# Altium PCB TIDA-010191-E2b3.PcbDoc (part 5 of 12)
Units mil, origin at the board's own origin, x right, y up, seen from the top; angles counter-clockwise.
Board outline 9842.52 x 9842.4 mil, 6 copper layers (Layer 1 - Top Layer, Layer 2 - GND Layer, Layer 3 - Signal, Layer 4 - Signal, Layer 5 - GND, Bottom Layer), stack 59.9 mil thick; 1178 components, 642 nets, 3329 pads, 2967 vias.
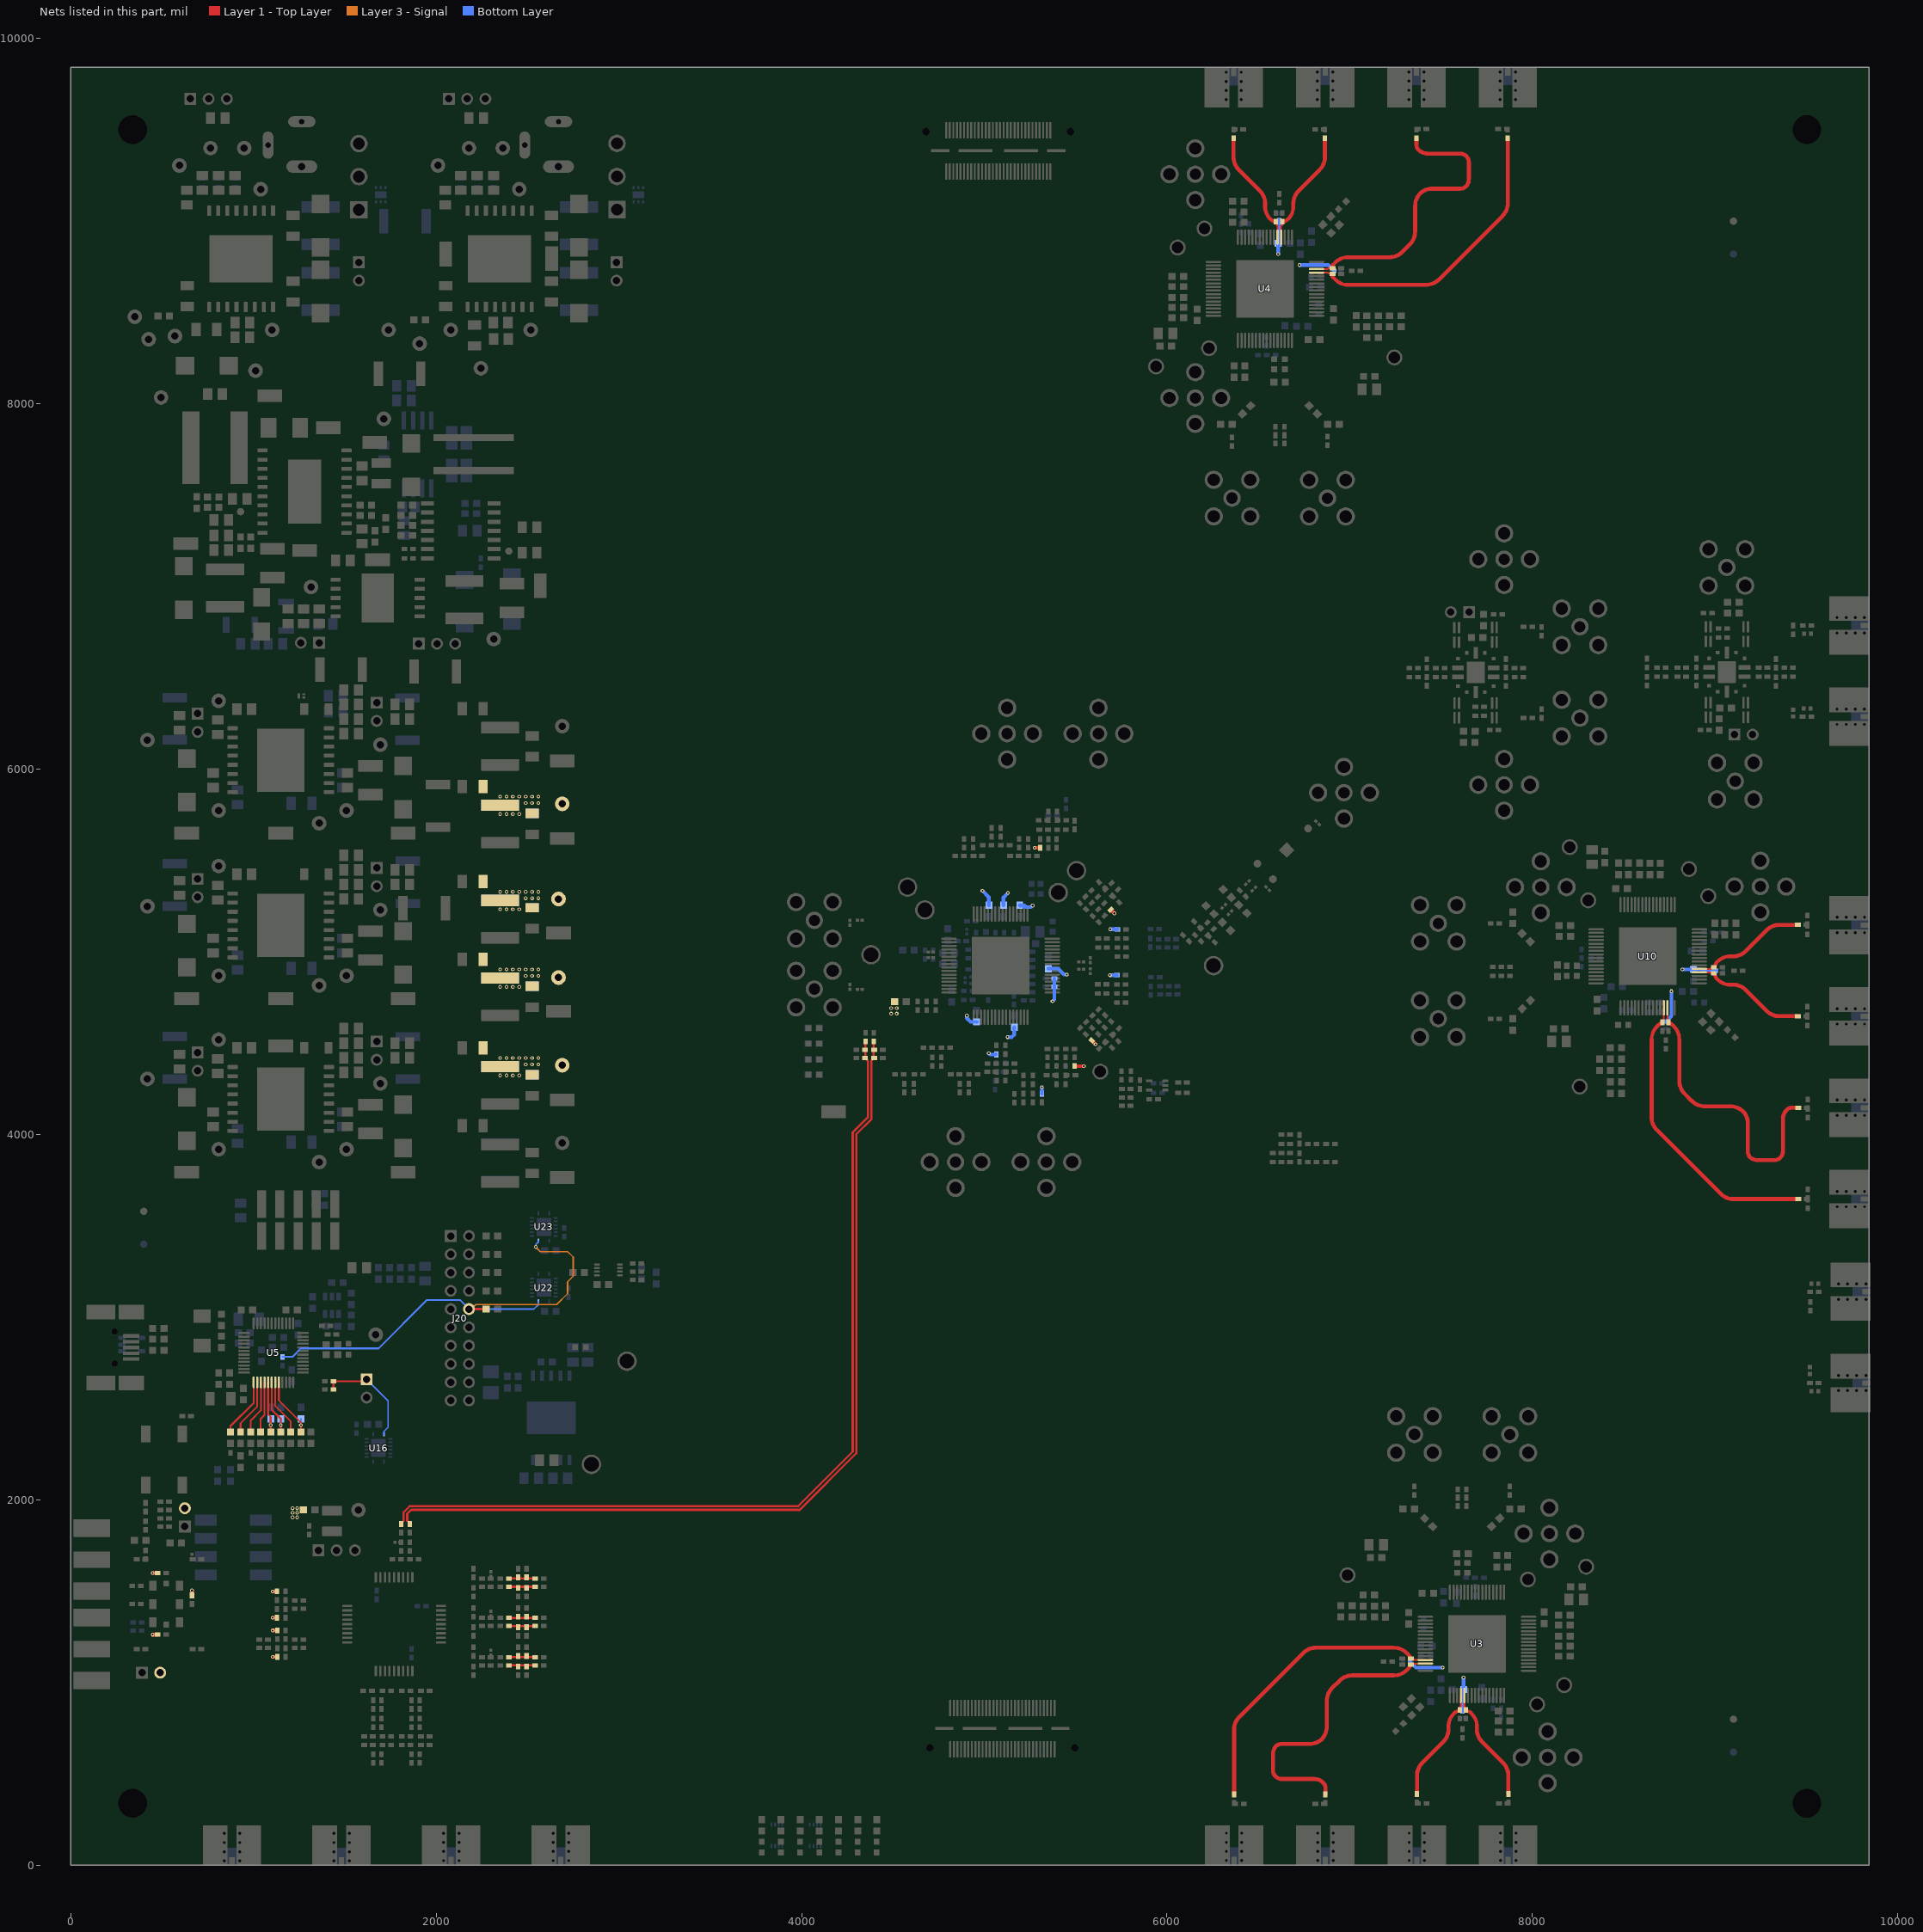
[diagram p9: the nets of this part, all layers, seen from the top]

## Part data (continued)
R5 R13 R14 R21 R22 R29 R30 R31 R32 R47 R48 R49 R50 R286 R287 R288 R289 R356: library part CMP-0026833-3, "RES, 120, 5%, 0.063 W, AEC-Q200 Grade 0, 0402", Manufacturer=Vishay-Dale, PartNumber=CRCW0402120RJNED, Power_W=63mW, Supplier Part Number 1=541-120JCT-ND, TempCo="200 ppm/C", Tolerance_%=5%, Value2=0.063W, Value_Code=120R, ValueDisplayed=120
R11 R12 R15 R16 R23 R24 R60 R61 R64 R65 R66 R67: library part CMP-0026882-3, "RES, 240, 5%, 0.063 W, AEC-Q200 Grade 0, 0402", Manufacturer=Vishay-Dale, PartNumber=CRCW0402240RJNED, Power_W=63mW, Supplier Part Number 1=541-240JCT-ND, TempCo="200 ppm/C", Tolerance_%=5%, Value2=0.063W, Value_Code=240R, ValueDisplayed=240
R17 R18 R58 R59: library part CMP-0026878-3, "RES, 220, 5%, 0.063 W, AEC-Q200 Grade 0, 0402", Manufacturer=Vishay-Dale, PartNumber=CRCW0402220RJNED, Power_W=63mW, Supplier Part Number 1=541-220JCT-ND, TempCo="200 ppm/C", Tolerance_%=5%, Value2=0.063W, Value_Code=220R, ValueDisplayed=220
R26 R68 R69 R71 R72 R73 R74 R75 R76 R81 R84 R92 R126 R127 R130 R132 R135 R136 R166 R203 R208 R209 R216 R233 R238 R239 R240 R242 R243 R244 R245 R246 R247 R249 R269 R271 R272 R273 R280 R295 R301 R316 R319 R325 R331 R332 R350 R352 R353 R355 R358 R359 R360 R389 R494 R497 R500: "RES, 0, 5%, 0.063 W, AEC-Q200 Grade 0, 0402", Manufacturer=Vishay-Dale, PartNumber=CRCW04020000Z0ED, Power_W=63mW, Supplier Part Number 1=541-0.0JCT-ND, TempCo="200 ppm/C", Tolerance_%=5%, Value2=0.063W, Value_Code=0000, ValueDisplayed=0
R28: library part CMP-0027814-1, "RES, 620, 1%, 0.05 W, 0201", Manufacturer="Yageo America", PartNumber=RC0201FR-07620RL, Power_W=50mW, Supplier Part Number 1=YAG2348CT-ND, TempCo="200 ppm/C", Tolerance_%=1%, Value2=0.05W, Value_Code=620R, ValueDisplayed=620
R34 R40 R270 R299: library part CMP-0025998-3, "RES, 130, 1%, 0.063 W, AEC-Q200 Grade 0, 0402", Manufacturer=Vishay-Dale, PartNumber=CRCW0402130RFKED, Power_W=63mW, Supplier Part Number 1=541-130LCT-ND, TempCo="100 ppm/C", Tolerance_%=1%, Value2=0.063W, Value_Code=130R, ValueDisplayed=130
R35 R343: library part CMP-0026658-1, "RES, 10.0 k, 1%, 0.1 W, 0402", Manufacturer=Panasonic, PartNumber=ERJ-2RKF1002X, Power_W=100mW, Supplier Part Number 1=P10.0KLCT-ND, TempCo="100 ppm/C", Tolerance_%=1%, Value2=0.1W, Value_Code=10k0, ValueDisplayed=10.0k
R36 R38 R180 R220: library part Resistor, "RES, 0, 5%, 0.063 W, 0402", Manufacturer=Panasonic, Power_W=63mW, Supplier Part Number 1=P0.0JCT-ND, TempCo="600 ppm/C", Tolerance_%=5%, Value2=0.063W, Value_Code=0000, ValueDisplayed=0
R43 R44 R51 R370: library part CMP-0026834-3, "RES, 12 k, 5%, 0.063 W, AEC-Q200 Grade 0, 0402", Manufacturer=Vishay-Dale, PartNumber=CRCW040212K0JNED, Power_W=63mW, Supplier Part Number 1=541-12KJCT-ND, TempCo="200 ppm/C", Tolerance_%=5%, Value2=0.063W, Value_Code=12k0, ValueDisplayed=12k
R52: library part CMP-0027649-1, "RES, 39.0 k, 1%, 0.05 W, 0201", Manufacturer="Yageo America", PartNumber=RC0201FR-0739KL, Power_W=50mW, Supplier Part Number 1=YAG2641CT-ND, TempCo="200 ppm/C", Tolerance_%=1%, Value2=0.05W, Value_Code=39k0, ValueDisplayed=39.0k
R53 R104 R113 R277 R318 R348 R351: library part CMP-0025825-4, "RES, 51, 5%, 0.1 W, AEC-Q200 Grade 0, 0603", Manufacturer=Vishay-Dale, PartNumber=CRCW060351R0JNEA, Power_W=100mW, Supplier Part Number 1=541-51GCT-ND, TempCo="200 ppm/C", Tolerance_%=5%, Value2=0.1W, Value_Code=51R0, ValueDisplayed=51
R77 R78 R79 R80: library part CMP-0022588-5, "RES, 750, 1%, 0.1 W, AEC-Q200 Grade 0, 0603", Manufacturer=Vishay-Dale, PartNumber=CRCW0603750RFKEA, Power_W=100mW, Supplier Part Number 1=541-750HCT-ND, TempCo="100 ppm/C", Tolerance_%=1%, Value2=0.1W, Value_Code=750R, ValueDisplayed=750
R82 R86 R93 R97 R224 R230 R258 R260 R261 R265 R315 R327: "RES, 50, 0.1%, 0.05 W, 0402", Manufacturer=Vishay-Dale, PartNumber=FC0402E50R0BST1, Power_W=50mW, Supplier Part Number 1=FC0402-50BWCT-ND, TempCo="25 ppm/C", Tolerance_%=0.1%, Value2=0.05W, Value_Code=50R0, ValueDisplayed=50
R83 R85 R87 R88 R89 R91 R107 R112 R178 R211 R212 R226 R227 R228 R231 R232 R235 R251 R252 R253 R254 R255 R256 R257 R259 R262 R281 R304 R317 R333 R354 R372 R559 R560: library part CMP-0025697-4, "RES, 0, 5%, 0.1 W, AEC-Q200 Grade 0, 0603", Manufacturer=Vishay-Dale, PartNumber=CRCW06030000Z0EA, Power_W=100mW, Supplier Part Number 1=541-0.0GCT-ND, TempCo="200 ppm/C", Tolerance_%=5%, Value2=0.1W, Value_Code=0000, ValueDisplayed=0
R90 R250 R274: library part CMP-0025698-4, "RES, 100 k, 5%, 0.1 W, AEC-Q200 Grade 0, 0603", Manufacturer=Vishay-Dale, PartNumber=CRCW0603100KJNEA, Power_W=100mW, Supplier Part Number 1=541-100KGCT-ND, TempCo="200 ppm/C", Tolerance_%=5%, Value2=0.1W, Value_Code=100k
R94 R263 R321: library part CMP-0025904-5, "RES, 270, 5%, 0.1 W, 0603", Manufacturer=Yageo, PartNumber=RC0603JR-07270RL, Power_W=100mW, Supplier Part Number 1=311-270GRCT-ND, TempCo="100 ppm/C", Tolerance_%=5%, Value2=0.1W, Value_Code=270R, ValueDisplayed=270
R95 R320: "RES, 0, 5%, 0.1 W, AEC-Q200 Grade 0, 0603", Manufacturer=Vishay-Dale, PartNumber=CRCW06030000Z0EA, Power_W=100mW, Supplier Part Number 1=541-0.0GCT-ND, TempCo="200 ppm/C", Tolerance_%=5%, Value2=0.1W, Value_Code=0000, ValueDisplayed=0
R96 R264 R322: library part CMP-0025710-4, "RES, 120, 5%, 0.1 W, AEC-Q200 Grade 0, 0603", Manufacturer=Vishay-Dale, PartNumber=CRCW0603120RJNEA, Power_W=100mW, Supplier Part Number 1=541-120GCT-ND, TempCo="200 ppm/C", Tolerance_%=5%, Value2=0.1W, Value_Code=120R, ValueDisplayed=120
R98 R101: "RES, 0, 5%, .05 W, AEC-Q200 Grade 0, 0201", Manufacturer=Panasonic, PartNumber=ERJ-1GN0R00C, Power_W=50mW, Supplier Part Number 1=P15979CT-ND, TempCo=ppm/C, Tolerance_%=5%, Value2=.05W, Value_Code=0000, ValueDisplayed=0
R99 R100: library part CMP-0027139-3, "RES, 51, 5%, 0.05 W, 0201", Manufacturer="Yageo America", Power_W=50mW, Supplier Part Number 1=311-51NCT-ND, TempCo="200 ppm/C", Tolerance_%=5%, Value2=0.05W, Value_Code=51R0, ValueDisplayed=51
R102 R109 R154 R156 R157 R158 R159 R181 R185 R186 R187 R188 R189 R206 R207 R225 R279 R300 R313 R349 R538 R539 R540 R541: "RES, 100, 1%, 0.1 W, AEC-Q200 Grade 0, 0603", Manufacturer=Vishay-Dale, PartNumber=CRCW0603100RFKEA, Power_W=100mW, Supplier Part Number 1=541-100HCT-ND, TempCo="100 ppm/C", Tolerance_%=1%, Value2=0.1W, Value_Code=100R, ValueDisplayed=100
R103 R106 R111 R117 R120 R164 R210 R361 R362 R363 R364 R553 R554 R555 R556: library part CMP-0065361-1, "RES, 0, 5%, .05 W, AEC-Q200 Grade 0, 0201", Manufacturer=Panasonic, Power_W=50mW, Supplier Part Number 1=P15979CT-ND, TempCo=ppm/C, Tolerance_%=5%, Value2=.05W, Value_Code=0000, ValueDisplayed=0
R105 R294 R314: library part CMP-0025912-5, "RES, 330, 5%, 0.1 W, 0603", Manufacturer=Yageo, PartNumber=RC0603JR-07330RL, Power_W=100mW, Supplier Part Number 1=311-330GRCT-ND, TempCo="100 ppm/C", Tolerance_%=5%, Value2=0.1W, Value_Code=330R, ValueDisplayed=330
R108 R110 R118 R119 R138 R378: library part CMP-0022448-4, "RES, 49.9, 1%, 0.1 W, AEC-Q200 Grade 0, 0603", Manufacturer=Vishay-Dale, Power_W=100mW, Supplier Part Number 1=541-49.9HCT-ND, TempCo="100 ppm/C", Tolerance_%=1%, Value2=0.1W, Value_Code=49R9, ValueDisplayed=49.9
R116 R143 R145 R168 R169 R170 R204 R215 R392: library part CMP-0025951-3, "RES, 100, 1%, 0.063 W, AEC-Q200 Grade 0, 0402", Manufacturer=Vishay-Dale, Power_W=63mW, Supplier Part Number 1=541-100LCT-ND, TempCo="100 ppm/C", Tolerance_%=1%, Value2=0.063W, Value_Code=100R, ValueDisplayed=100
R121 R131 R373 R374: library part CMP-0026368-2, "RES, 40.2, 1%, 0.063 W, AEC-Q200 Grade 0, 0402", Manufacturer=Vishay-Dale, Power_W=63mW, Supplier Part Number 1=541-40.2LCT-ND, TempCo="100 ppm/C", Tolerance_%=1%, Value2=0.063W, Value_Code=40R2, ValueDisplayed=40.2
R122 R128 R323 R328: library part CMP-0026159-2, "RES, 200, 1%, 0.063 W, AEC-Q200 Grade 0, 0402", Manufacturer=Vishay-Dale, Power_W=63mW, Supplier Part Number 1=541-200LCT-ND, TempCo="100 ppm/C", Tolerance_%=1%, Value2=0.063W, Value_Code=200R, ValueDisplayed=200
R123 R129 R329 R330: library part CMP-0026853-5, "RES, 1.1 k, 5%, 0.063 W, AEC-Q200 Grade 0, 0402", Manufacturer=Vishay-Dale, Power_W=63mW, Supplier Part Number 1=541-1.1KJCT-ND, TempCo="200 ppm/C", Tolerance_%=5%, Value2=0.063W, Value_Code=1k10, ValueDisplayed=1.1k
R124 R125 R324 R326: library part CMP-0025994-3, "RES, 12.1, 1%, 0.063 W, AEC-Q200 Grade 0, 0402", Manufacturer=Vishay-Dale, Power_W=63mW, Supplier Part Number 1=541-12.1LCT-ND, TempCo="100 ppm/C", Tolerance_%=1%, Value2=0.063W, Value_Code=12R1, ValueDisplayed=12.1
R133 R134 R375 R376: library part CMP-0026822-3, "RES, 0, 5%, 0.063 W, AEC-Q200 Grade 0, 0402", Manufacturer=Vishay-Dale, Power_W=63mW, Supplier Part Number 1=541-0.0JCT-ND, TempCo="200 ppm/C", Tolerance_%=5%, Value2=0.063W, Value_Code=0000, ValueDisplayed=0
R137 R140 R377 R379: library part CMP-0022109-5, "RES, 1.00 k, 1%, 0.1 W, AEC-Q200 Grade 0, 0603", Manufacturer=Vishay-Dale, Power_W=100mW, Supplier Part Number 1=541-1.00KHCT-ND, TempCo="100 ppm/C", Tolerance_%=1%, Value2=0.1W, Value_Code=1k00, ValueDisplayed=1.00k
R139 R175 R380: library part CMP-0026658-1, "RES, 10.0 k, 1%, 0.1 W, 0402", Manufacturer=Panasonic, Power_W=100mW, Supplier Part Number 1=P10.0KLCT-ND, TempCo="100 ppm/C", Tolerance_%=1%, Value2=0.1W, Value_Code=10k0, ValueDisplayed=10.0k
R147: library part CMP-0025794-4, "RES, 39 k, 5%, 0.1 W, AEC-Q200 Grade 0, 0603", Manufacturer=Vishay-Dale, PartNumber=CRCW060339K0JNEA, Power_W=100mW, Supplier Part Number 1=541-39KGCT-ND, TempCo="200 ppm/C", Tolerance_%=5%, Value2=0.1W, Value_Code=39k0, ValueDisplayed=39k
R149 R150: library part CMP-0022004-4, "RES, 10.0, 1%, 0.25 W, AEC-Q200 Grade 0, 0603", Manufacturer=Vishay-Dale, PartNumber=CRCW060310R0FKEAHP, Power_W=250mW, Supplier Part Number 1=541-10.0SCT-ND, TempCo="100 ppm/C", Tolerance_%=1%, Value2=0.25W, Value_Code=10R0, ValueDisplayed=10.0
R151 R152 R160 R161 R162 R205 R308 R309 R310 R312 R405: library part CMP-0025701-4, "RES, 10 k, 5%, 0.1 W, AEC-Q200 Grade 0, 0603", Manufacturer=Vishay-Dale, PartNumber=CRCW060310K0JNEA, Power_W=100mW, Supplier Part Number 1=541-10KGCT-ND, TempCo="200 ppm/C", Tolerance_%=5%, Value2=0.1W, Value_Code=10k0, ValueDisplayed=10k
R153: "RES, 12 k, 5%, 0.1 W, AEC-Q200 Grade 0, 0603", Manufacturer=Vishay-Dale, PartNumber=CRCW060312K0JNEA, Power_W=100mW, Supplier Part Number 1=541-12KGCT-ND, TempCo="200 ppm/C", Tolerance_%=5%, Value2=0.1W, Value_Code=12k0, ValueDisplayed=12k
R155: library part CMP-0026412-2, "RES, 4.75 k, 1%, 0.063 W, AEC-Q200 Grade 0, 0402", Manufacturer=Vishay-Dale, Power_W=63mW, Supplier Part Number 1=541-4.75KLCT-ND, TempCo="100 ppm/C", Tolerance_%=1%, Value2=0.063W, Value_Code=4k75, ValueDisplayed=4.75k
R163: library part CMP-0025768-4, "RES, 2.0 k, 5%, 0.1 W, AEC-Q200 Grade 0, 0603", Manufacturer=Vishay-Dale, PartNumber=CRCW06032K00JNEA, Power_W=100mW, Supplier Part Number 1=541-2.0KGCT-ND, TempCo="200 ppm/C", Tolerance_%=5%, Value2=0.1W, Value_Code=2k00, ValueDisplayed=2.0k
R171: library part CMP-0023294-5, "RES, 82.0, 1%, 0.1 W, 0603", Manufacturer=Yageo, PartNumber=RC0603FR-0782RL, Power_W=100mW, Supplier Part Number 1=311-82.0HRCT-ND, TempCo="100 ppm/C", Tolerance_%=1%, Value2=0.1W, Value_Code=82R0, ValueDisplayed=82.0
R174: library part CMP-0025958-3, "RES, 10.0 k, 1%, 0.063 W, AEC-Q200 Grade 0, 0402", Manufacturer=Vishay-Dale, Power_W=63mW, Supplier Part Number 1=541-10.0KLCT-ND, TempCo="100 ppm/C", Tolerance_%=1%, Value2=0.063W, Value_Code=10k0, ValueDisplayed=10.0k
R177 R179 R198 R199: library part CMP-0026575-2, "RES, 82.5, 1%, 0.063 W, AEC-Q200 Grade 0, 0402", Manufacturer=Vishay-Dale, Power_W=63mW, Supplier Part Number 1=541-82.5LCT-ND, TempCo="100 ppm/C", Tolerance_%=1%, Value2=0.063W, Value_Code=82R5, ValueDisplayed=82.5
R190: library part CMP-0026936-3, "RES, 47, 5%, 0.063 W, AEC-Q200 Grade 0, 0402", Manufacturer=Vishay-Dale, PartNumber=CRCW040247R0JNED, Power_W=63mW, Supplier Part Number 1=541-47JCT-ND, TempCo="200 ppm/C", Tolerance_%=5%, Value2=0.063W, Value_Code=47R0, ValueDisplayed=47
R213 R214 R267 R268: library part CMP-0026769-2, "RES, 10.0 k, 0.5%, 0.063 W, AEC-Q200 Grade 0, 0402", Manufacturer=Vishay-Dale, PartNumber=CRCW040210K0DHEDP, Power_W=63mW, Supplier Part Number 1=541-10KAVCT-ND, TempCo="50 ppm/C", Tolerance_%=0.5%, Value2=0.063W, Value_Code=10k0, ValueDisplayed=10.0k
R217: library part CMP-0022109-5, "RES, 1.00 k, 1%, 0.1 W, AEC-Q200 Grade 0, 0603", Manufacturer=Vishay-Dale, PartNumber=CRCW06031K00FKEA, Power_W=100mW, Supplier Part Number 1=541-1.00KHCT-ND, TempCo="100 ppm/C", Tolerance_%=1%, Value2=0.1W, Value_Code=1k00, ValueDisplayed=1.00k
R282 R283 R292 R293: library part CMP-0026164-2, "RES, 20.0, 1%, 0.063 W, AEC-Q200 Grade 0, 0402", Manufacturer=Vishay-Dale, PartNumber=CRCW040220R0FKED, Power_W=63mW, Supplier Part Number 1=541-20.0LCT-ND, TempCo="100 ppm/C", Tolerance_%=1%, Value2=0.063W, Value_Code=20R0, ValueDisplayed=20.0
R296 R302 R303 R305 R306 R307 R311: library part CMP-0025787-4, "RES, 33, 5%, 0.1 W, AEC-Q200 Grade 0, 0603", Manufacturer=Vishay-Dale, PartNumber=CRCW060333R0JNEA, Power_W=100mW, Supplier Part Number 1=541-33GCT-ND, TempCo="200 ppm/C", Tolerance_%=5%, Value2=0.1W, Value_Code=33R0, ValueDisplayed=33
R334: library part CMP-0026769-2, "RES, 10.0 k, 0.5%, 0.063 W, AEC-Q200 Grade 0, 0402", Manufacturer=Vishay-Dale, Power_W=63mW, Supplier Part Number 1=541-10KAVCT-ND, TempCo="50 ppm/C", Tolerance_%=0.5%, Value2=0.063W, Value_Code=10k0, ValueDisplayed=10.0k
R342: "RES, 10.0 k, 0.5%, 0.063 W, AEC-Q200 Grade 0, 0402", Manufacturer=Vishay-Dale, PartNumber=CRCW040210K0DHEDP, Power_W=63mW, Supplier Part Number 1=541-10KAVCT-ND, TempCo="50 ppm/C", Tolerance_%=0.5%, Value2=0.063W, Value_Code=10k0, ValueDisplayed=10.0k
R383: library part CMP-0025697-4, "RES, 0, 5%, 0.1 W, AEC-Q200 Grade 0, 0603", Manufacturer=Vishay-Dale, Power_W=100mW, Supplier Part Number 1=541-0.0GCT-ND, TempCo="200 ppm/C", Tolerance_%=5%, Value2=0.1W, Value_Code=0000, ValueDisplayed=0
R384 R385: library part CMP-0020616-3, "RES, 0, 5%, 0.125 W, AEC-Q200 Grade 0, 0805", Manufacturer=Panasonic, Power_W=125mW, Supplier Part Number 1=P0.0ACT-ND, TempCo="600 ppm/C", Tolerance_%=5%, Value2=0.125W, Value_Code=0000, ValueDisplayed=0
R386 R387 R557 R558: library part CMP-0020446-3, "RES, 10 k, 5%, 0.125 W, AEC-Q200 Grade 0, 0805", Manufacturer=Vishay-Dale, Power_W=125mW, Supplier Part Number 1=541-10KACT-ND, TempCo="200 ppm/C", Tolerance_%=5%, Value2=0.125W, Value_Code=10k0, ValueDisplayed=10k
R388: library part CMP-0020593-3, "RES, 750, 5%, 0.125 W, AEC-Q200 Grade 0, 0805", Manufacturer=Vishay-Dale, Power_W=125mW, Supplier Part Number 1=541-750ACT-ND, TempCo="200 ppm/C", Tolerance_%=5%, Value2=0.125W, Value_Code=750R, ValueDisplayed=750
R395 R396 R428 R429 R438 R439 R448 R449 R458 R459 R468 R469: library part CMP-0026981-3, "RES, 82, 5%, 0.063 W, AEC-Q200 Grade 0, 0402", Manufacturer=Vishay-Dale, Power_W=63mW, Supplier Part Number 1=541-82JCT-ND, TempCo="200 ppm/C", Tolerance_%=5%, Value2=0.063W, Value_Code=82R0, ValueDisplayed=82
R397 R398 R399 R400 R430 R431 R432 R433 R440 R441 R442 R443 R450 R451 R452 R453 R460 R461 R462 R463 R470 R471 R472 R473: library part CMP-0026992-3, "RES, 0, 5%, 0.1 W, AEC-Q200 Grade 0, 0402", Manufacturer=Panasonic, Power_W=100mW, Supplier Part Number 1=P0.0JCT-ND, TempCo="600 ppm/C", Tolerance_%=5%, Value2=0.1W, Value_Code=0000, ValueDisplayed=0
R401 R402 R434 R435 R444 R445 R454 R455 R464 R465 R474 R475: library part CMP-0026022-3, "RES, 150, 1%, 0.063 W, AEC-Q200 Grade 0, 0402", Manufacturer=Vishay-Dale, Power_W=63mW, Supplier Part Number 1=541-150LCT-ND, TempCo="100 ppm/C", Tolerance_%=1%, Value2=0.063W, Value_Code=150R, ValueDisplayed=150
R403 R404 R436 R437 R446 R447 R456 R457 R466 R467 R476 R477: library part CMP-0025998-3, "RES, 130, 1%, 0.063 W, AEC-Q200 Grade 0, 0402", Manufacturer=Vishay-Dale, Power_W=63mW, Supplier Part Number 1=541-130LCT-ND, TempCo="100 ppm/C", Tolerance_%=1%, Value2=0.063W, Value_Code=130R, ValueDisplayed=130
R407: library part CMP-0015099-2, "RES, 0.05, 1%, 6 W, 4320_WIDE", Manufacturer="Susumu Co Ltd", Power_W=6W, Supplier Part Number 1=KRL11C.050CT-ND, TempCo="50 ppm/C", Tolerance_%=1%, Value_Code=R050, ValueDisplayed=0.05
R408 R410 R424 R425: library part CMP-0019441-2, "RES, 100 k, 0.1%, 0.125 W, 0805", Manufacturer="Yageo America", Power_W=125mW, TempCo="25 ppm/C", Tolerance_%=0.1%, Value2=0.125W, Value_Code=100k
R409: library part CMP-0022707-2, "RES, 49.9, 1%, 0.1 W, AEC-Q200 Grade 0, 0603", Manufacturer=Panasonic, PartNumber=ERJ-3EKF49R9V, Power_W=100mW, Supplier Part Number 1=P49.9HCT-ND, TempCo="100 ppm/C", Tolerance_%=1%, Value2=0.1W, Value_Code=49R9, ValueDisplayed=49.9
R411 R412: library part CMP-0022684-3, "RES, 10.0 k, 1%, 0.1 W, 0603", Manufacturer=Panasonic, PartNumber=ERJ-3EKF1002V, Power_W=100mW, Supplier Part Number 1=P10.0KHCT-ND, TempCo="100 ppm/C", Tolerance_%=1%, Value2=0.1W, Value_Code=10k0, ValueDisplayed=10.0k
R413: library part CMP-0023646-2, "RES, 10.1 k, 0.1%, 0.1 W, 0603", Manufacturer="Yageo America", PartNumber=RT0603BRD0710K1L, Power_W=100mW, TempCo="25 ppm/C", Tolerance_%=0.1%, Value2=0.1W, Value_Code=10k1, ValueDisplayed=10.1k
R414: library part CMP-0022659-4, "RES, 95.3 k, 1%, 0.1 W, AEC-Q200 Grade 0, 0603", Manufacturer=Vishay-Dale, PartNumber=CRCW060395K3FKEA, Power_W=100mW, Supplier Part Number 1=541-95.3KHCT-ND, TempCo="100 ppm/C", Tolerance_%=1%, Value2=0.1W, Value_Code=95k3, ValueDisplayed=95.3k
R415: library part CMP-0024083-3, "RES, 2.84 k, 0.1%, 0.1 W, 0603", Manufacturer="Yageo America", Power_W=100mW, TempCo="25 ppm/C", Tolerance_%=0.1%, Value2=0.1W, Value_Code=2k84, ValueDisplayed=2.84k
R416 R426: library part CMP-0022001-4, "RES, 10.7 k, 1%, 0.1 W, AEC-Q200 Grade 0, 0603", Manufacturer=Vishay-Dale, Power_W=100mW, Supplier Part Number 1=541-10.7KHCT-ND, TempCo="100 ppm/C", Tolerance_%=1%, Value2=0.1W, Value_Code=10k7, ValueDisplayed=10.7k
R417 R427: library part CMP-0022018-4, "RES, 11.5 k, 1%, 0.1 W, AEC-Q200 Grade 0, 0603", Manufacturer=Vishay-Dale, Power_W=100mW, Supplier Part Number 1=541-11.5KHCT-ND, TempCo="100 ppm/C", Tolerance_%=1%, Value2=0.1W, Value_Code=11k5, ValueDisplayed=11.5k
R418 R479: library part CMP-0022325-4, "RES, 30.9 k, 1%, 0.1 W, AEC-Q200 Grade 0, 0603", Manufacturer=Vishay-Dale, Power_W=100mW, Supplier Part Number 1=541-30.9KHCT-ND, TempCo="100 ppm/C", Tolerance_%=1%, Value2=0.1W, Value_Code=30k9, ValueDisplayed=30.9k
R419 R480: library part CMP-0024481-2, "RES, 7.59 k, 0.1%, 0.1 W, 0603", Manufacturer="Yageo America", Power_W=100mW, TempCo="25 ppm/C", Tolerance_%=0.1%, Value2=0.1W, Value_Code=7k59, ValueDisplayed=7.59k
R420: library part CMP-0022985-5, "RES, 2.26 k, 1%, 0.1 W, 0603", Manufacturer=Yageo, PartNumber=RC0603FR-072K26L, Power_W=100mW, Supplier Part Number 1=311-2.26KHRCT-ND, TempCo="100 ppm/C", Tolerance_%=1%, Value2=0.1W, Value_Code=2k26, ValueDisplayed=2.26k
R421: library part CMP-0022376-4, "RES, 3.40 k, 1%, 0.1 W, AEC-Q200 Grade 0, 0603", Manufacturer=Vishay-Dale, PartNumber=CRCW06033K40FKEA, Power_W=100mW, Supplier Part Number 1=541-3.40KHCT-ND, TempCo="100 ppm/C", Tolerance_%=1%, Value2=0.1W, Value_Code=3k40, ValueDisplayed=3.40k
R422 R423 R502 R503 R514 R515 R525 R526 R527 R528 R545 R546: library part CMP-0080698-1, "RES, 0, 0%, 1 W, AEC-Q200 Grade 0, 2512", Manufacturer=Kamaya, Power_W=1W, Supplier Part Number 1=791-RMC1JPTE, Tolerance_%=0%, Value_Code=0
R485: library part CMP-0020442-3, "RES, 0, 5%, 0.125 W, AEC-Q200 Grade 0, 0805", Manufacturer=Vishay-Dale, Power_W=125mW, Supplier Part Number 1=541-0.0ACT-ND, TempCo="200 ppm/C", Tolerance_%=5%, Value2=0.125W, Value_Code=0000, ValueDisplayed=0
R486 R489 R490 R491: library part CMP-0020442-3, "RES, 0, 5%, 0.125 W, AEC-Q200 Grade 0, 0805", Manufacturer=Vishay-Dale, PartNumber=CRCW08050000Z0EA, Power_W=125mW, Supplier Part Number 1=541-0.0ACT-ND, TempCo="200 ppm/C", Tolerance_%=5%, Value2=0.125W, Value_Code=0000, ValueDisplayed=0
R487 R488 R507: library part CMP-0021614-3, "RES, 20.0 k, 1%, 0.125 W, AEC-Q200 Grade 0, 0805", Manufacturer=Panasonic, PartNumber=ERJ-6ENF2002V, Power_W=125mW, Supplier Part Number 1=P20.0KCCT-ND, TempCo="100 ppm/C", Tolerance_%=1%, Value2=0.125W, Value_Code=20k0, ValueDisplayed=20.0k
R492: library part CMP-0019984-1, "RES, 352 k, 0.1%, 0.125 W, 0805", Manufacturer="Yageo America", Power_W=125mW, TempCo="25 ppm/C", Tolerance_%=0.1%, Value2=0.125W, Value_Code=352k
R493 R496 R499: library part CMP-0023653-3, "RES, 10.0 k, 0.1%, 0.1 W, 0603", Manufacturer="Yageo America", Power_W=100mW, TempCo="25 ppm/C", Tolerance_%=0.1%, Value2=0.1W, Value_Code=10k0, ValueDisplayed=10.0k
R495 R498 R501: library part CMP-0023358-4, "RES, 10 M, 0.5%, 0.1 W, AEC-Q200 Grade 0, 0603", Manufacturer=Vishay-Dale, Power_W=100mW, Supplier Part Number 1=541-10MAYCT-ND, TempCo="50 ppm/C", Tolerance_%=0.5%, Value2=0.1W, Value_Code=10M0, ValueDisplayed=10M
R504 R516 R529: library part CMP-0017563-3, "RES, 3.65 k, 1%, 0.25 W, AEC-Q200 Grade 0, 1206", Manufacturer=Panasonic, Power_W=250mW, Supplier Part Number 1=P3.65KFCT-ND, TempCo="100 ppm/C", Tolerance_%=1%, Value2=0.25W, Value_Code=3k65, ValueDisplayed=3.65k
R505 R513 R517 R524 R530 R537: library part CMP-0079710-1, "RES, 49.9, 1%, 0.15 W, 0805", Manufacturer="TT Electronics/IRC", Power_W=150mW, TempCo="100 ppm/C", Tolerance_%=1%, Value2=0.15W, Value_Code=49R9, ValueDisplayed=49.9
R506: library part CMP-0021042-3, "RES, 20.0 k, 1%, 0.125 W, AEC-Q200 Grade 0, 0805", Manufacturer=Vishay-Dale, Power_W=125mW, Supplier Part Number 1=541-20.0KCCT-ND, TempCo="100 ppm/C", Tolerance_%=1%, Value2=0.125W, Value_Code=20k0, ValueDisplayed=20.0k
R508 R510 R519 R521 R532 R534 R549 R551: library part CMP-0081857-1, "RES, 0, 0%,  W, AEC-Q200 Grade 0, 0805", Manufacturer=Rohm, Supplier Part Number 1=755-PMR10EZPJ000, Tolerance_%=0%, Value2=W, Value_Code=0
R509 R520 R533: library part CMP-0020154-2, "RES, 51.1 k, 0.1%, 0.125 W, 0805", Manufacturer="Yageo America", Power_W=125mW, TempCo="25 ppm/C", Tolerance_%=0.1%, Value2=0.125W, Value_Code=51k1, ValueDisplayed=51.1k
R511 R512 R522 R523 R535 R536: library part CMP-0019490-2, "RES, 11.5 k, 0.1%, 0.125 W, 0805", Manufacturer="Yageo America", Power_W=125mW, Supplier Part Number 1=9983007, TempCo="25 ppm/C", Tolerance_%=0.1%, Value2=0.125W, Value_Code=11k5, ValueDisplayed=11.5k
R518 R531: "RES, 20.0 k, 1%, 0.125 W, AEC-Q200 Grade 0, 0805", Manufacturer=Panasonic, PartNumber=ERJ-6ENF2002V, Power_W=125mW, Supplier Part Number 1=P20.0KCCT-ND, TempCo="100 ppm/C", Tolerance_%=1%, Value2=0.125W, Value_Code=20k0, ValueDisplayed=20.0k
R542 R543 R544: library part CMP-0022839-5, "RES, 178, 1%, 0.1 W, 0603", Manufacturer=Yageo, Power_W=100mW, Supplier Part Number 1=311-178HRCT-ND, TempCo="100 ppm/C", Tolerance_%=1%, Value2=0.1W, Value_Code=178R, ValueDisplayed=178
R547 R552: library part CMP-0020126-2, "RES, 49.9, 0.1%, 0.125 W, 0805", Manufacturer="Yageo America", Power_W=125mW, TempCo="25 ppm/C", Tolerance_%=0.1%, Value2=0.125W, Value_Code=49R9, ValueDisplayed=49.9
R548: library part CMP-0020387-2, "RES, 8.66 k, 0.1%, 0.125 W, 0805", Manufacturer="Yageo America", Power_W=125mW, TempCo="25 ppm/C", Tolerance_%=0.1%, Value2=0.125W, Value_Code=8k66, ValueDisplayed=8.66k
R550: library part CMP-0020035-2, "RES, 3.20 k, 0.1%, 0.125 W, 0805", Manufacturer="Yageo America", Power_W=125mW, Supplier Part Number 1=9982949, TempCo="25 ppm/C", Tolerance_%=0.1%, Value2=0.125W, Value_Code=3k20, ValueDisplayed=3.20k
S1 S2 S3 S4: library part CMP-0003647-1, "HEX STANDOFF SPACER, 9.53 mm", Manufacturer="Richco Plastics", PartNumber=TCBS-6-01, Supplier Part Number 1=TCBS-6-01-ND
S7 S8: "SWITCH SLIDE SPST 4A PCB, TH", CurrentRating_mA=4kA, Manufacturer="C&K Components", PartNumber=L101011MS02Q, Supplier Part Number 1=CKC5106-ND
SH-J1 SH-J2 SH-J3 SH-J4 SH-J30: library part CMP-0003642-1, "Shunt, 100mil, Flash Gold, Black", Manufacturer="Sullins Connector Solutions", Supplier Part Number 1=S9001-ND
TP1 TP2 TP3 TP4 TP9 TP10 TP83 TP84: library part CMP-0055119-1, "Terminal, Turret, TH, Double", Manufacturer=Keystone, Supplier Part Number 1=36-1573-2-ND
TP5 TP22 TP23 TP24 TP25 TP26 TP36 TP43 TP48 TP49 TP50 TP51 TP56 TP61 TP62 TP63 TP64 TP69 TP74 TP75 TP76 TP77 TP80 TP81 TP82: library part CMP-0055152-2, "Test Point, Miniature, SMT", Manufacturer="Keystone Electronics", Supplier Part Number 1=36-5015TR-ND
TP8 TP12 TP13 TP28 TP39 TP40 TP41 TP46 TP52 TP53 TP54 TP59 TP65 TP66 TP67 TP72 TP78 TP79 VCCCORE: library part CMP-0055137-2, "Test Point, Miniature, Red, TH", Color=Red, Manufacturer="Keystone Electronics", Supplier Part Number 1=36-5000-ND
TP11 TP15 TP16 TP17 TP18 TP19 TP20 TP21 TP27 TP29 TP30 TP31 TP32 TP33 TP34 TP35 TP37 TP42 TP44 TP45 TP47 TP55 TP57 TP58 TP60 TP68 TP70 TP71 TP73: library part CMP-0055139-2, "Test Point, Miniature, White, TH", Color=White, Manufacturer="Keystone Electronics", Supplier Part Number 1=36-5002-ND
TP14 TP38: library part CMP-0003825-1, "1mm Test Point, SMT", Manufacturer=Any
U1: library part CMP-0088226-3, "Space Grade Ultra-Low-Noise JESD204B Dual-Loop Clock Jitter Cleaner", Manufacturer="Texas Instruments", Operating Temperature Range="-55°C to +125°C"
U2: "Ultra-Low Jitter Fully Programmable Oscillator, Integrated EEPROM, +/-50ppm, SIA0008B (QFM-8)", Alternate Manufacturer="Texas Instruments", Alternate PartNumber=LMK61E2-SIAT, PartNumber=LMK61E2-SIAR
U3 U4 U10: library part CMP-0013512-3, "Space Grade 40 MHz to 15 GHz Wideband Synthesizer with Phase Synchronization and JESD204B Support, HBD0064A (CFP-64)", Alternate Manufacturer="Texas Instruments", Operating Temperature Range="-55 to 125 C"
U5: "Single Channel Hi-Speed USB to Multipurpose UART/FIFO IC, LQFP-48", Manufacturer=FTDI, Supplier Part Number 1=768-1101-1-ND
U6 U11: library part CMP-0074610-5, "Radiation Hardness Assured (RHA) 6.5GHz Ultra Wideband Fully Differential Amplifier, FFK0014A (LCCC-14)", Alternate Manufacturer="Texas Instruments", Operating Temperature Range="25 to 25 C", Rating=Space
U7: library part CMP-0005251-2, "2K Microwire Compatible Serial EEPROM, SOT-23-6", Manufacturer=Microchip, Supplier Part Number 1=93LC56BT-I/OTCT-ND
U9: library part CMP-0081033-1, "Low-Voltage 1:10 LVPECL With Selectable Input Clock Driver, HFG0036A (CFP-36)", Alternate Manufacturer="Texas Instruments"
U14: library part CMP-0051584-3, "Single 2-Input Positive-AND Gate, DCK0005A, LARGE T&R", F @ Nom Voltage(Max)(Mhz)=150, Generic Part Number=SN74LVC1G08, ICC @ Nom Voltage(Max)(mA)=0.01, Manufacturer="Texas Instruments", Operating Temperature Range(C)="-40 to 125,-40 to 85", Rating=Catalog, tpd @ Nom Voltage(Max)(ns)=4.5,6,4,5, Voltage(Nom)(V)=1.8,2.5,3.3,5
U16 U22 U23: library part CMP-0066254-2, "Low-Voltage 4-Bit 1-Of-2 FET Multiplexer/Demultiplexer, RGY0016A (VQFN-16)", Alternate Manufacturer="Texas Instruments"
U17: library part CMP-0860295-1, "Automotive Catalog Single 5-Ohm SP3T Analog Switch 5-V/3.3-V 3:1 Analog Multiplexer/Demultiplexer, DCU0008A (VSSOP-8)", Alternate Manufacturer="Texas Instruments", Operating Temperature Range="-40 to 125 C", Rating=Automotive
U20: library part CMP-0085632-1, "3.6V Data-Line Surge and 30kV ESD Protection Diode Array, DBV0005A (SOT-23-5)", Alternate Manufacturer="Texas Instruments", Operating Temperature Range="-40 to 125 C", Rating=Catalog
U21: library part CMP-0077675-3, "Space Grade High-Accuracy Remote and Local Temperature Sensor with Pin-Programmable Bus Address, HKU0010A (CFP-10)", Alternate Manufacturer="Texas Instruments"
U24 U27: library part CMP-0078485-2, "Radiation Hardened 7-V, 6-A Load Switch, HKR0016A (CFP-16)", Alternate Manufacturer="Texas Instruments", Rating=Space
U25: library part CMP-0077088-1, "Radiation Hardened 3.0- to 6.3-V Input, 6-A Synchronous Buck Converter, HKH0020A (CFP-20)", Alternate Manufacturer="Texas Instruments"
U26 U28: library part CMP-0077837-1, "5-V Precision Surge Protection Clamp, DRV0006A (WSON-6)", Alternate Manufacturer="Texas Instruments"
U29: library part CMP-0081563-2, "Voltage Output, Unidirectional Measurement Current-Shunt Monitor, HKX0008A (CFP-8)", Alternate Manufacturer="Texas Instruments", Rating=Space
U30: library part CMP-0068426-2, "Low Power Low Offset Voltage Quad Comparator, NAC0014A (CFP-14)", Manufacturer="Texas Instruments", Operating Temperature Range="-55 to 125 C", Rating=Space
U31 U32 U33: library part CMP-0860535-1, "1.5 -7V Input, 3 Amp, Ultra Low Dropout Regulator, HKR0016A (CFP-16)", Alternate Manufacturer="Texas Instruments"
U34 U36: library part CMP-0051942-2, "Triple Inverter Buffer/Driver with Open-Drain Output, DCU0008A (VSSOP-8)", F @ Nom Voltage(Max)(Mhz)=150, Generic Part Number=SN74LVC3G06, ICC @ Nom Voltage(Max)(mA)=0.01, Manufacturer="Texas Instruments", Operating Temperature Range="-40 to 125 C", Rating=Catalog, tpd @ Nom Voltage(Max)(ns)=7.8,4.5,4,3.5, Voltage(Nom)(V)=1.8,2.5,3.3,5
U35: library part CMP-0067526-3, "Wide Vin Low-Dropout Voltage Regulator, HKU0010A (CFP-10)", Alternate Manufacturer="Texas Instruments", Operating Temperature Range="25 to 25 C", Rating=Space
U37: library part CMP-0089709-1, "Power Divider, 4 Way-0 , 0.001 to 0.5 GHz, 50 ohms, SMT", Manufacturer=Mini-Circuits, Mouser Part Number=139-AD4PS-1, Operating Temperature Range="-40°C to +85°C"
U40: library part CMP-0065379-3, "Broadband Balun, 500 kHz to 6 GHz", Manufacturer="Marki Microwave"
Y1: "VCXO, 100 MHz, 3.3V, SMD", Frequency_Fixed=100MHz, Frequency Stability=+/-20ppm, Manufacturer="Crystek Corporation", PartNumber=CVHD-950-100.000, Supplier Part Number 1=744-1213-ND
Y2: library part CMP-0004616-3, "Crystal, 12 MHz, 18 pF, SMD", Frequency_Fixed=12MHz, Frequency Stability=+/-30ppm, Manufacturer="Abracon Corporation", Supplier Part Number 1=535-10634-1-ND
ZZ1: library part CMP-0003616-3
ZZ2: library part CMP-0077236-1
ZZ3: library part CMP-0077237-1
ZZ4: library part CMP-0077238-1

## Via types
v1: diameter 20, hole 10, Layer 1 - Top Layer to Bottom Layer, tented both sides, 2595 vias
v2: diameter 19.68, hole 7.87, Layer 1 - Top Layer to Bottom Layer, 308 vias
v3: diameter 19.68, hole 7.87, Layer 1 - Top Layer to Bottom Layer, tented both sides, 25 vias
v4: diameter 20, hole 10, Layer 1 - Top Layer to Bottom Layer, 21 vias
v5: diameter 41, hole 25, Layer 1 - Top Layer to Bottom Layer, 10 vias
v6: diameter 24, hole 12, Layer 1 - Top Layer to Bottom Layer, tented both sides, 4 vias
v7: diameter 24, hole 8, Layer 1 - Top Layer to Bottom Layer, tented both sides, 1 vias
v8: diameter 24/24/24/24/24/24 (per signal layer), hole 8, Layer 1 - Top Layer to Bottom Layer, tented both sides, 1 vias
v9: diameter 30, hole 12, Layer 1 - Top Layer to Bottom Layer, tented both sides, 1 vias
v10: diameter 20/20/20/20/20/20 (per signal layer), hole 10, Layer 1 - Top Layer to Bottom Layer, tented both sides, 1 vias

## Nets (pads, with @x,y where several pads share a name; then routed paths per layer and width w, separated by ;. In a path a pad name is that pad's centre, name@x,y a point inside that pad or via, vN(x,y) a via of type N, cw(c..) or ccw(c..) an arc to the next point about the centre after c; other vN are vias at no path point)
+3.3V_CDCM7005: C339.2 C340.2 C341.1 C342.1 L17.1 L29.2 TP72.1
  other v1: 1215,1905 1240,1905 1215,1930 1240,1930 1215,1955 1240,1955 2350,4809.21 2385,4809.21 2420,4809.21 2455,4809.21 2490,4869.21 2525,4869.21 2560,4869.21 2350,4904.21 2385,4904.21 2420,4904.21 2455,4904.21 2490,4904.21 2525,4904.21 2560,4904.21
+3.3V_LMXRF: C299.2 C300.2 C301.1 C302.1 L11.1 L12.1 L18.1 L19.1 L21.1 L22.1 L27.2 R235.1 R252.1 R372.1 TP59.1 | length 1144.2
  Bottom Layer w20: v1(6608.5,8820) R252.1@6608.5,8880 6615,8886.5 L18.1@6615,9006.3 ; v1(6725,8760) 6882.96,8760 L19.1@6915.56,8727.4 ; L12.1@7328.9,1116.31 7362.8,1082.4 v1(7509.26,1082.4) ; L11.1@7616.1,842.67 7616.1,962.47 7622.6,968.97 v1(7622.6,1028.97) ; L22.1@8731,4618.7 8761,4648.7 v1(8761,4785) ; v1(8820.5,4904.04) 8925.84,4904.04 8932.34,4897.55 L21.1@9006.8,4897.55
  other v1: 2350,5755 2385,5755 2420,5755 2455,5755 2490,5815 2525,5815 2560,5815 2350,5850 2385,5850 2420,5850 2455,5850 2490,5850 2525,5850 2560,5850
+3.3V_VCO: C305.2 C306.2 C307.1 C308.1 J8.2 J16.2 L28.2 R43.2 R44.2 R51.1 TP67.1 | length 81.8
  Layer 1 - Top Layer w20: v1(448.21,1263.12) R43.2@475.47,1263.12 ; v1(449.12,1600) R44.2@476.38,1600 ; R51.1@664.09,1477.74 v1(664.09,1505)
  other v1: 2350,5234.21 2385,5234.21 2420,5234.21 2455,5234.21 2490,5294.21 2525,5294.21 2560,5294.21 2350,5329.21 2385,5329.21 2420,5329.21 2455,5329.21 2490,5329.21 2525,5329.21 2560,5329.21
+3.3VLMK: C267.2 C268.2 C269.1 C270.1 L2.2 L4.2 L5.2 L7.2 L8.2 L9.2 L10.2 L24.2 R114.2 R115.2 R177.1 R179.1 R190.2 R198.1 R199.1 R284.2 R290.2 R336.1 R338.2 R343.2 R344.2 R346.1 TP41.1 | length 1043.4
  Layer 1 - Top Layer w20: v1(1105,1355.38) R199.1@1130,1355.38 ; v1(1105,1499.62) R198.1@1130,1499.62 ; v1(1106,1141.38) R179.1@1131,1141.38 ; v1(1106,1285.62) R177.1@1131,1285.62 ; v1(5275,5570) 5304.62,5570 R346.1@5305,5570.38 ; R338.2@5495,4376.38 5496.38,4375 v1(5545,4375) ; R284.2@5588.7,4515.3 v1(5608.7,4495.3) ; R114.2@5691.7,5231.7 v1(5711.7,5211.7)
  Bottom Layer w20: v1(4905,4651.5) 4905,4637.52 4925,4617.52 4958.11,4617.52 L9.2@4958.62,4617.01 ; v1(4990,5335) 5025,5300 L8.2@5025,5256.5 ; v1(5025,4445) 5031.38,4438.62 5061.06,4438.62 R344.2@5063.03,4440.59 ; L7.2@5105,5256.5 5105,5298 v1(5130,5323) ; v1(5127.11,4534.05) 5150.84,4534.05 5163.5,4546.72 5163.5,4587.01 L10.2@5165,4588.5 ; L4.2@5194.17,5256.5 5197.17,5253.5 5219.78,5253.5 5227.58,5245.71 5255.71,5245.71 5263.5,5253.5 v1(5265,5253.5) ; v1(5315,4260) 5315,4224.15 R336.1@5315.21,4223.94 ; L2.2@5350.93,4908.69 5403.42,4908.69 5436.27,4875.83 v1(5451.38,4875.83) v1@5451.54,4875.83 ; v1(5373.62,4730) 5383.62,4740 R343.2@5383.62,4810 R190.2@5383.62,4855 ; v1(5688,4873.09) R290.2@5726.27,4873.09 ; v1(5690,5124.09) R115.2@5728.27,5124.09
  other v1: 2350,4324.21 2385,4324.21 2420,4324.21 2455,4324.21 2490,4384.21 2525,4384.21 2560,4384.21 2350,4419.21 2385,4419.21 2420,4419.21 2455,4419.21 2490,4419.21 2525,4419.21 2560,4419.21 4490.61,4662.52 4520.61,4662.52 4490.61,4692.52 4520.61,4692.52
ACBUS0: J20.10 R340.1 R405.2 U22.1 U23.1 | length 2728.6
  Layer 1 - Top Layer w13.5: J20.10@2180,3045 R405.2@2273.5,3045
  Layer 3 - Signal w8: J20.10@2180,3045 2192.9,3045 2217.9,3070 2660,3070 2720,3130 2720,3195 2750,3225 2750,3330 2720,3360 2570,3360 v1(2545,3385)
  Bottom Layer w8: J20.10@2186.45,3045 2535,3045 2560.47,3070.47 U22.1@2560.47,3087.76 ; v1(2545,3385) 2547.3,3387.3 2547.3,3399.93 2560.47,3413.11 U23.1@2560.47,3420.2
  Bottom Layer w10: R340.1@1160,2783.48 1213.48,2783.48 1260,2830 1685,2830 1950,3095 2130,3095 J20.10@2180,3045 J20.10@2186.45,3045
ACBUS1: J39.1 R341.1 R370.1 U16.1 | length 589.9
  Layer 1 - Top Layer w10: R370.1@1438.62,2605 R341.1@1438.62,2650.59 1610,2650.59 J39.1@1620,2660.59
  Bottom Layer w8: J39.1@1620,2660.59 1737.26,2543.33 1737.26,2397.74 1714.53,2375 U16.1@1714.53,2359.8
ADBUS0: R178.1 U5.13 | length 324.6
  Layer 1 - Top Layer w10: R178.1@875,2372.09 875,2405 1001.73,2531.73 U5.13@1001.73,2644.17
ADBUS1: R154.1 U5.14 | length 310
  Layer 1 - Top Layer w10: R154.1@930,2372.09 930,2420 1021.42,2511.42 U5.14@1021.42,2644.17
ADBUS2: R212.1 U5.15 | length 295.3
  Layer 1 - Top Layer w10: R212.1@985,2372.09 985,2435 1041.1,2491.1 U5.15@1041.1,2644.17
ADBUS3: R156.1 U5.16 | length 280.7
  Layer 1 - Top Layer w10: R156.1@1040,2372.09 1040,2445 1060.79,2465.79 U5.16@1060.79,2644.17
ADBUS4: R151.1 R157.1 U5.17 | length 312.2
  Layer 1 - Top Layer w10: U5.17@1080.47,2644.17 1080.47,2469.53 1095,2455 v1(1095,2410) R157.1@1095,2372.09
  Bottom Layer w10: v1(1095,2410) R151.1@1095,2444.09
ADBUS5: R152.1 R158.1 U5.18 | length 326.8
  Layer 1 - Top Layer w10: U5.18@1100.16,2644.17 1100.16,2494.84 1150,2445 v1(1150,2410) R158.1@1150,2372.09
  Bottom Layer w10: v1(1150,2410) R152.1@1150,2444.09
ADBUS6: R159.1 U5.19 | length 307.4
  Layer 1 - Top Layer w10: U5.19@1119.84,2644.17 1119.84,2515.16 1205,2430 R159.1@1205,2372.09
ADBUS7: R181.1 R205.1 U5.20 | length 356.1
  Layer 1 - Top Layer w10: U5.20@1139.53,2644.17 1139.53,2545.47 1260,2425 v1(1260,2410) R181.1@1260,2372.09
  Bottom Layer w10: v1(1260,2410) R205.1@1260,2444.09
ADC_CLK1+: C44.2 R82.1 U3.37 | length 630.1
  Layer 1 - Top Layer w9.84: U3.37@7627.36,930.47 7627.34,869.22 7632.6,863.96 R82.1@7632.6,847.15
  Layer 1 - Top Layer w12: 7666.28,831.77 7666.66,831.39
  Layer 1 - Top Layer w20: R82.1@7636.02,845.1 cw(c7633.97,799.46) 7666.28,831.77 ; 7666.66,831.39 cw(c7595.95,760.68) 7695.54,769.71
  Layer 1 - Top Layer w22: 7695.54,769.71 7695.54,746.7 ccw(c7795.54,746.7) 7699.47,718.94 ccw(c7795.54,746.7) 7724.14,676.68 ; 7724.83,675.99 7838.9,561.92 cw(c7768.19,491.21) 7868.19,491.21 C44.2@7868.19,390.94
ADC_CLK1-: C48.2 R86.2 U3.36 | length 631
  Layer 1 - Top Layer w9.84: R86.2@7602.4,847.15 7602.4,863.96 7607.66,869.22 U3.36@7607.66,930.47
  Layer 1 - Top Layer w12: 7511.54,675.99 ccw(c7440.83,746.7) 7512.23,676.68 ; 7569.71,831.39 7570.09,831.77
  Layer 1 - Top Layer w20: 7540.83,769.71 cw(c7640.42,760.68) 7569.71,831.39 ; 7570.09,831.77 cw(c7602.4,799.46) R86.2@7600.35,845.1
  Layer 1 - Top Layer w22: C48.2@7368.19,390.94 7368.19,491.21 cw(c7468.19,491.21) 7397.48,561.92 7511.54,675.99 ; 7512.23,676.68 ccw(c7440.83,746.7) 7536.9,718.94 ccw(c7440.83,746.7) 7540.83,746.7 7540.83,769.71
ADC_CLK2+: C118.2 R258.1 U4.37 | length 630.1
  Layer 1 - Top Layer w9.84: R258.1@6599.75,8995.83 6599.75,8979.02 6605.01,8973.77 U4.37@6604.99,8912.51
  Layer 1 - Top Layer w12: 6565.69,9011.6 6566.07,9011.22
  Layer 1 - Top Layer w20: 6536.81,9073.27 ccw(c6636.4,9082.31) 6565.69,9011.6 ; 6566.07,9011.22 ccw(c6598.38,9043.52) R258.1@6596.33,8997.88
  Layer 1 - Top Layer w22: C118.2@6364.17,9452.05 6364.17,9351.77 ccw(c6464.17,9351.77) 6393.45,9281.06 6507.52,9166.99 ; 6508.21,9166.3 cw(c6436.81,9096.28) 6532.88,9124.05 cw(c6436.81,9096.28) 6536.81,9096.28 6536.81,9073.28
ADC_CLK2-: C141.2 R260.2 U4.36 | length 631
  Layer 1 - Top Layer w9.84: U4.36@6624.7,8912.51 6624.7,8973.77 6629.95,8979.02 R260.2@6629.95,8995.83
  Layer 1 - Top Layer w12: 6662.26,9011.22 6662.64,9011.6 ; 6720.12,9166.3 cw(c6791.52,9096.28) 6720.81,9166.99
  Layer 1 - Top Layer w20: R260.2@6632,8997.88 ccw(c6629.95,9043.52) 6662.26,9011.22 ; 6662.64,9011.6 ccw(c6591.93,9082.31) 6691.52,9073.27
  Layer 1 - Top Layer w22: 6691.52,9073.28 6691.52,9096.28 cw(c6791.52,9096.28) 6695.45,9124.04 cw(c6791.52,9096.28) 6720.12,9166.3 ; 6720.81,9166.99 6834.88,9281.06 ccw(c6764.17,9351.77) 6864.17,9351.77 C141.2@6864.17,9452.05
ADC_CLK3+: C153.2 R224.1 U10.37 | length 630.1
  Layer 1 - Top Layer w9.84: U10.37@8913.01,4907.56 8974.26,4907.56 8979.52,4912.82 R224.1@8996.33,4912.82
  Layer 1 - Top Layer w12: 9011.71,4946.5 9012.09,4946.88
  Layer 1 - Top Layer w20: R224.1@8998.38,4916.24 cw(c9044.02,4914.19) 9011.71,4946.5 ; 9012.09,4946.88 cw(c9082.81,4876.17) 9073.77,4975.76
  Layer 1 - Top Layer w22: 9073.77,4975.76 9096.78,4975.76 ccw(c9096.78,5075.76) 9124.54,4979.69 ccw(c9096.78,5075.76) 9166.8,5004.36 ; 9167.49,5005.05 9281.56,5119.11 cw(c9352.27,5048.4) 9352.27,5148.4 C153.2@9452.54,5148.38
ADC_CLK3-: C158.2 R230.2 U10.36 | length 633.9
  Layer 1 - Top Layer w9.84: U10.36@8913.01,4887.85 8974.26,4887.85 8979.52,4882.6 R230.2@8996.33,4882.6
  Layer 1 - Top Layer w12: 9011.71,4850.29 9012.09,4849.91 ; 9166.8,4792.43 cw(c9096.78,4721.03) 9167.49,4791.74
  Layer 1 - Top Layer w20: R230.2@8996.33,4882.6 8998.38,4880.55 ccw(c9044.02,4882.6) 9011.71,4850.29 ; 9012.09,4849.91 ccw(c9082.81,4920.62) 9073.77,4821.03
  Layer 1 - Top Layer w22: 9073.77,4821.03 9096.78,4821.03 cw(c9096.78,4721.03) 9124.54,4817.1 cw(c9096.78,4721.03) 9166.8,4792.42 ; 9167.49,4791.74 9281.56,4677.67 ccw(c9352.27,4748.38) 9352.27,4648.38 C158.2@9452.54,4648.38
ADC_SYSREF1+: C57.2 R93.1 U3.29 | length 1631
  Layer 1 - Top Layer w8: 7237.82,1191.26 7241.55,1191.26
  Layer 1 - Top Layer w9.84: R93.1@7330.46,1129.63 7347.27,1129.63 7352.52,1124.37 U3.29@7413.78,1124.37
  Layer 1 - Top Layer w20: 7241.55,1191.26 cw(c7241.55,1091.26) 7312.26,1161.97 7321.98,1152.25 cw(c7301.53,1131.8) R93.1@7330.46,1131.8
  Layer 1 - Top Layer w22: C57.2@6367.17,388.47 C57.2@6367.17,388.47 6367.1,743.27 cw(c6467.1,743.27) 6396.39,813.98 6744.39,1161.97 cw(c6815.1,1091.26) 6815.1,1191.26 7237.82,1191.26
ADC_SYSREF1-: C64.2 R97.2 U3.30 | length 1628.8
  Layer 1 - Top Layer w9.84: R97.2@7330.46,1099.43 R97.2@7334.39,1099.43 7347.27,1099.43 7352.52,1104.68 U3.30@7413.78,1104.69
  Layer 1 - Top Layer w20: 7241.55,1039.96 ccw(c7241.55,1139.96) 7312.26,1069.25 7321.98,1078.97 ccw(c7301.53,1099.43) R97.2@7330.46,1099.43
  Layer 1 - Top Layer w22: 6628.87,664.89 ccw(c6628.87,613.67) 6597.91,654.47 ccw(c6641.05,611.33) 6580.04,611.33 6580.04,519.27 ccw(c6624.43,519.27) 6593.04,487.89 ccw(c6629.26,524.1) 6629.26,472.89 6805.29,472.89 cw(c6805.29,401.19) 6855.99,451.89 cw(c6829.01,424.9) 6867.17,424.9 C64.2@6867.17,388.47 ; 6629.26,664.89 6780.57,664.89 ccw(c6780.57,764.89) 6842.92,686.71 6845.07,688.85 ccw(c6774.36,759.56) 6874.36,759.56 6874.36,899.58 cw(c6974.36,899.58) 6903.65,970.29 6944.02,1010.67 cw(c7014.74,939.96) 7014.74,1039.96 7241.55,1039.96
ADC_SYSREF2+: C142.2 R315.1 U4.29 | length 1631
  Layer 1 - Top Layer w8: 6990.8,8651.72 6994.53,8651.72
  Layer 1 - Top Layer w9.84: U4.29@6818.57,8718.61 6879.83,8718.61 6885.08,8713.36 R315.1@6901.89,8713.36
  Layer 1 - Top Layer w20: R315.1@6901.89,8711.18 ccw(c6930.82,8711.18) 6910.37,8690.73 6920.09,8681.01 ccw(c6990.8,8751.72) 6990.8,8651.72
  Layer 1 - Top Layer w22: 6994.53,8651.72 7417.25,8651.72 ccw(c7417.25,8751.72) 7487.96,8681.01 7835.96,9029.01 ccw(c7765.25,9099.72) 7865.25,9099.72 7865.25,9454.44 C142.2@7865.19,9454.51
ADC_SYSREF2-: C192.2 R327.2 U4.30 | length 1628.8
  Layer 1 - Top Layer w9.84: U4.30@6818.57,8738.3 6879.83,8738.3 6885.08,8743.56 R327.2@6901.89,8743.56
  Layer 1 - Top Layer w20: R327.2@6901.89,8743.56 cw(c6930.82,8743.56) 6910.37,8764.01 6920.09,8773.73 cw(c6990.8,8703.02) 6990.8,8803.02
  Layer 1 - Top Layer w22: 6990.8,8803.02 7217.62,8803.02 ccw(c7217.62,8903.02) 7288.33,8832.31 7328.71,8872.69 ccw(c7258,8943.4) 7358,8943.4 7358,9083.42 cw(c7458,9083.42) 7387.28,9154.13 7389.43,9156.28 cw(c7451.78,9078.1) 7451.78,9178.1 7603.1,9178.1 ; C192.2@7365.19,9454.51 7365.19,9418.08 ccw(c7403.35,9418.08) 7376.36,9391.1 ccw(c7427.06,9441.79) 7427.06,9370.1 7603.1,9370.1 cw(c7603.1,9318.88) 7639.31,9355.1 cw(c7607.92,9323.71) 7652.31,9323.71 7652.31,9231.65 cw(c7591.3,9231.65) 7634.44,9188.51 cw(c7603.48,9229.31) 7603.48,9178.1
ADC_SYSREF3+: C166.2 R261.1 U10.29 | length 1631
  Layer 1 - Top Layer w8: 8652.22,4518.01 8652.22,4521.75
  Layer 1 - Top Layer w9.84: R261.1@8713.85,4610.65 8713.85,4627.46 8719.11,4632.72 U10.29@8719.11,4693.98
  Layer 1 - Top Layer w20: 8652.22,4521.75 cw(c8752.22,4521.75) 8681.51,4592.46 8691.23,4602.18 cw(c8711.68,4581.72) R261.1@8711.68,4610.65
  Layer 1 - Top Layer w22: 8652.22,4518.01 8652.22,4095.29 ccw(c8752.22,4095.29) 8681.51,4024.58 9029.5,3676.59 ccw(c9100.21,3747.3) 9100.21,3647.3 9454.94,3647.3 C166.2@9455.01,3647.36
ADC_SYSREF3-: C181.2 R265.2 U10.30 | length 1628.8
  Layer 1 - Top Layer w9.84: U10.30@8738.8,4693.98 8738.8,4632.72 8744.05,4627.46 R265.2@8744.05,4614.59 R265.2@8744.05,4610.65
  Layer 1 - Top Layer w20: R265.2@8744.05,4610.65 cw(c8744.05,4581.72) 8764.51,4602.18 8774.23,4592.46 cw(c8703.52,4521.75) 8803.52,4521.75
  Layer 1 - Top Layer w22: 8803.52,4521.75 8803.52,4294.93 ccw(c8903.52,4294.93) 8832.81,4224.22 8873.19,4183.84 ccw(c8943.9,4254.55) 8943.9,4154.55 9083.92,4154.55 cw(c9083.92,4054.55) 9154.63,4125.26 9156.77,4123.12 cw(c9078.59,4060.76) 9178.59,4060.76 9178.59,3909.45 ; 9178.59,3909.07 ccw(c9229.81,3909.07) 9189.01,3878.11 ccw(c9232.15,3921.25) 9232.15,3860.24 9324.21,3860.24 ccw(c9324.21,3904.62) 9355.59,3873.24 ccw(c9319.38,3909.45) 9370.59,3909.45 9370.59,4085.49 cw(c9442.29,4085.49) 9391.59,4136.19 cw(c9418.58,4109.2) 9418.58,4147.36 C181.2@9455.01,4147.36
C1_N: C319.1 R439.1 R443.1 R447.2 | length 4949.6
  Layer 1 - Top Layer w12: C319.1@1855,1868.62 1855,1874 1842,1887 1842,1924.46 1863.83,1946.3 3989.58,1946.3 4300,2256.72 4300,4003.27 4383,4086.27 4383,4404.39 4395,4416.38 R443.1@4395,4510.14
C1_P: C318.1 R438.1 R441.1 R446.2 | length 4949.6
  Layer 1 - Top Layer w12: C318.1@1810,1868.62 1810,1874 1822,1886 1822,1932.75 1855.55,1966.3 3981.3,1966.3 4280,2265 4280,4011.55 4363,4094.55 4363,4403.38 4350,4416.38 R441.1@4350,4510.14
C2_N: C321.1 R449.1 R453.1 R457.2 | length 142.8
  Layer 1 - Top Layer w12: C321.1@2398.62,1525 R453.1@2541.38,1525
C2_P: C320.1 R448.1 R451.1 R456.2 | length 142.8
  Layer 1 - Top Layer w12: C320.1@2398.62,1570 R451.1@2541.38,1570
C3_N: C323.1 R459.1 R463.1 R467.2 | length 142.8
  Layer 1 - Top Layer w12: C323.1@2398.62,1310 R463.1@2541.38,1310
C3_P: C322.1 R458.1 R461.1 R466.2 | length 142.8
  Layer 1 - Top Layer w12: C322.1@2398.62,1355 R461.1@2541.38,1355
C4_N: C324.1 R468.1 R471.1 R476.2 | length 142.8
  Layer 1 - Top Layer w12: C324.1@2398.62,1095 R471.1@2541.38,1095
C4_P: C325.1 R469.1 R473.1 R477.2 | length 142.8
  Layer 1 - Top Layer w12: C325.1@2398.62,1140 R473.1@2541.38,1140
